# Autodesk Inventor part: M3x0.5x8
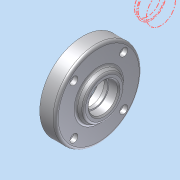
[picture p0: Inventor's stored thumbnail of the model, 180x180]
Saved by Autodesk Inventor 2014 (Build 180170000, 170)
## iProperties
Company: 한국ATC센터
Created: 2009-02
Part Number: M3x0.5x8
Document SubType Name: Modeling
Designer: KYOUNG IL JANG
Density: 2.71 g/cm^3
Mass: 97.9591 g
Surface Area: 115.525 cm^2
Volume: 36.1473 cm^3
Material: 알루미늄-6061
Vendor: CBT Solutions
Appearance: 알루미늄 - 평지
Author: KYOUNG IL JANG
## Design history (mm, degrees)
sketch "스케치1"
  geometry: L1 (-10.5, 0)-(10.5, 0); L2 (10.5, 0)-(10.5, 22.5); L3 (10.5, 22.5)-(5.5, 22.5); L4 (5.5, 22.5)-(5.5, 32.5); L5 (5.5, 32.5)-(-6.5, 32.5); L6 (-6.5, 32.5)-(-6.5, 17.5); L7 (-6.5, 17.5)-(-10.5, 15.191); L8 (-10.5, 15.191)-(-10.5, 0); 2 further points
  constraints: 16 end point, 3 parallel, 3 perpendicular, 1 coincident, 1 horizontal, 1 midpoint
  dimensions: "d0" = 21 distance of L1.start L1.end; "d1" = 65 diameter of L5 L1; "d2" = 45 diameter of L3 L1; "d3" = 35 diameter of L6.end L1; "d4" = 120 deg angle of L7 L6; "d5" = 12 distance of L4.end L5.end; "d6" = 5 distance of L2.end L3.end
revolve "회전1" sketch "스케치1" stored, may be unused: angle "d7" = 90 deg
sketch "스케치2"
  geometry: L1 (0, 0)-(32.5, 0); L2 (0, 0)-(18.738, 18.738); 1 further point
  constraints: 4 end point, 1 horizontal, 1 horizontal alignment, 1 other
  dimensions: "d8" = 45 deg angle of L1 L2; "d9" = 26.5 distance of L1.start L2.end
hole "구멍1" sketch "스케치2" at (18.738, 18.738) diameter "d10" = 3.4; stored, may be unused: countersink angle "d14" = 90 deg, drill point angle "d16" = 118 deg; dims "d11" = 6, "d12" = 6, "d13" = 3.3, "d15" = 8
fillet "모깎기1" dims "d20" = 2
hole "구멍2" diameter "d23" = 15; stored, may be unused: countersink angle "d27" = 90 deg, drill point angle "d29" = 0 deg; dims "d21" = 10, "d22" = 10, "d24" = 6, "d25" = 35, "d26" = 11, "d28" = 14
chamfer "모따기1" distance "d39" = 1; stored, may be unused: second distance "d40" = 2, angle "d41" = 45 deg
fillet "모깎기2" dims "d42" = 0.3
hole "구멍4" diameter "d46" = 17; stored, may be unused: countersink angle "d50" = 90 deg, drill point angle "d52" = 118 deg; dims "d44" = 10, "d45" = 10, "d47" = 6, "d48" = 22, "d49" = 7.3, "d51" = 8
chamfer "모따기2" distance "d53" = 1; stored, may be unused: second distance "d54" = 2, angle "d55" = 45 deg
fillet "모깎기3" dims "d56" = 0.3
node "솔리드1"
pattern_circular "원형 패턴1" dims angle "d18" = 360 deg
